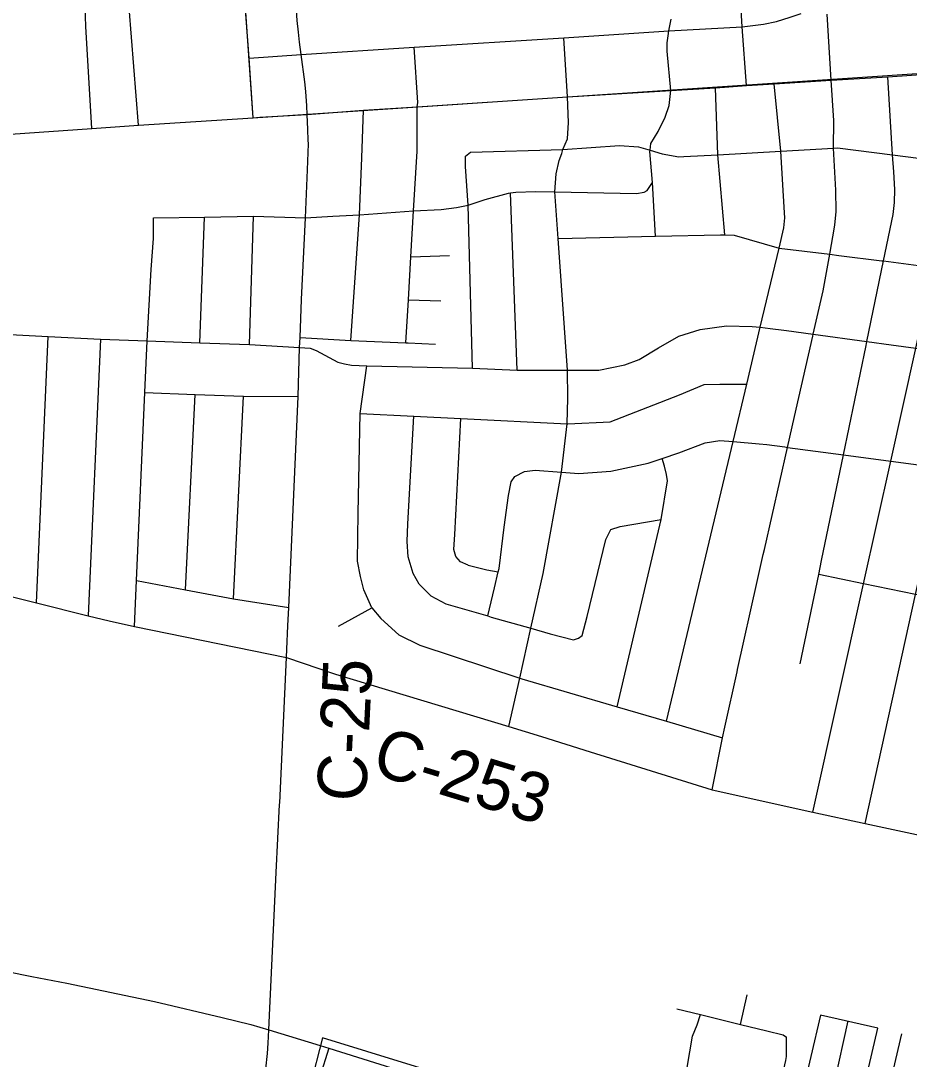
# Model space of a CAD drawing. Extents: x 114604 to 551442, y 316898 to 567001.
# Drawn here: x 179238 to 184654, y 374135 to 380464 of the extents above; entities that cross this region are included whole.
import ezdxf

# ---------------------------------------------------------------- set-up
doc = ezdxf.new("R2010")
doc.units = 0
for name, color, linetype in [('GE_P_Alignment_1000_Bearings', 7, 'Continuous'), ('GE_P_Alignment_1000_Cardinal_Points', 7, 'Continuous'), ('GE_P_Alignment_100_Cardinal_Points', 7, 'Continuous'), ('GE_P_Alignment_100_Stations', 7, 'Continuous'), ('GE_P_Alignment_500_Bearings', 7, 'Continuous'), ('PM_P_CL_Double_Solid', 7, 'Continuous')]:
    doc.layers.add(name, color=color, linetype=linetype)

msp = doc.modelspace()

# ---------------------------------------------------------------- linework, layer by layer
at = {"layer": 'GE_P_Alignment_1000_Bearings'}
msp.add_lwpolyline([(180378.1, 383822), (180652.5, 379872.3), (185830.5, 380217.5), (192483.8, 381831.8), (195789.4, 382643.8)], dxfattribs=at)
at = {"layer": 'GE_P_Alignment_1000_Cardinal_Points'}
for p, q in [((180242.2, 376996.6), (180301.3, 378187)), ((180534.3, 376941.6), (180595.8, 378175.4)), ((184046.5, 373297.2), (184282.2, 374369.4))]:
    msp.add_line(p, q, dxfattribs=at)
for points in [[(179930.4, 376772.8), (179943, 377053), (179994.6, 378199.2), (180009.2, 378512.3)], [(179994.6, 378199.2), (180301.3, 378187), (180595.8, 378175.4), (180928.6, 378174)], [(179943, 377053), (180242.2, 376996.6), (180534.3, 376941.6), (180871.4, 376888.8)], [(179777.4, 376805.9), (179930.4, 376772.8), (180857.5, 376583.8)], [(181115.8, 374201.6), (181061.3, 374027), (181007, 373892.1), (180965.1, 373818.1), (180956.9, 373777)]]:
    msp.add_lwpolyline(points, dxfattribs=at)
at = {"layer": 'GE_P_Alignment_100_Cardinal_Points'}
for p, q in [((184177.5, 380101.9), (184153.7, 380504.6)), ((182570.4, 380000.1), (182548.8, 380360.2)), ((181316.2, 379629.1), (181327, 379919)), ((182264.8, 378334.7), (182222.8, 379414.7)), ((180329.9, 378500.8), (180357.8, 379267.7)), ((180632, 378490.8), (180657, 379272.7)), ((181616.2, 379025.4), (181850.7, 379032.8)), ((181600.8, 378763.7), (181798.5, 378758)), ((179333.5, 376915.9), (179404.4, 378539.7)), ((179723.7, 378522.6), (179649, 376837.7)), ((181175.8, 376774.3), (181377.3, 376886.7)), ((183624.3, 374347.1), (183666.5, 374526.7))]:
    msp.add_line(p, q, dxfattribs=at)
for points in [[(180654.5, 379873.4), (180629.4, 380235.2), (180575.6, 380963.4), (180568.2, 381231.3), (180516.2, 381894.2), (180505.6, 382061.7), (180446, 382995.3), (180418, 383602.1), (180405.8, 383786.8)], [(183662, 380068.7), (183636.1, 380427.5), (183599.3, 381040.8), (183546, 381930.4)], [(179956, 379827.5), (179870.3, 380903.5), (179851.1, 381185.6), (179803.3, 381885.5)], [(180629.4, 380235.2), (180946.9, 380257.8), (181635.9, 380304.1), (182548.8, 380360.2), (183189.1, 380403), (183636.1, 380427.5), (183764.4, 380443.6), (183845.2, 380460.4), (183928.6, 380487), (183994.8, 380508.6)], [(183106.3, 379150.8), (183088.7, 379477.5), (183073.1, 379667.9), (183073.7, 379674.7), (183077.7, 379716.3), (183123.2, 379788.7), (183166, 379876.7), (183191.4, 379946.7), (183199.6, 380038.4), (183177.7, 380279.8), (183179.2, 380329.1), (183184.1, 380371.7), (183189.1, 380403), (183202.1, 380473.4)], [(180695.7, 379875.9), (180983.9, 379893.8), (181327, 379919), (181654.1, 379939.6), (182570.4, 380000.1), (183199.6, 380038.4), (183472, 380056), (183662, 380068.7), (183831.3, 380079.5), (184177.5, 380101.9), (184522.6, 380123.3), (184869.8, 380146.3), (185213.5, 380166.9), (185252.7, 380169.5), (185597, 380191.3), (185743.5, 380202), (185829.7, 380209.9), (185924.8, 380228.7), (185970, 380239.9), (186241.5, 380305.7), (186523.9, 380376), (186874.2, 380460.2), (186904.6, 380468)], [(181654.1, 379939.6), (181659.2, 379966.5), (181635.9, 380304.1)], [(184385.1, 375571.7), (184692.3, 376967), (184862, 377737.9), (185008.9, 378404.6), (185012.7, 378422.1), (185122, 378918.6), (185216.4, 379347.3), (185238.5, 379465.3), (185234.5, 379558.6), (185229.9, 379668.1), (185213.5, 380166.9)], [(183989.1, 376545.4), (184101.7, 377089.4), (184119.3, 377174.6), (184252.6, 377818.8), (184390.5, 378485.5), (184395.5, 378509.6), (184497, 378999.9), (184555.5, 379282.4), (184564.8, 379356.5), (184566.1, 379434.8), (184560, 379543.2), (184552.5, 379646.6), (184522.6, 380123.3)], [(184066.1, 375640.6), (184375, 377032.7), (184540.9, 377780.5), (184691.3, 378458.4), (184693.4, 378468.1), (184802.6, 378960.2), (184859.1, 379215), (184885, 379316.9), (184889.6, 379469.3), (184884.6, 379603.7), (184869.8, 380146.3)], [(184188.1, 379147.7), (184200.9, 379218.9), (184209.2, 379301.1), (184205.8, 379431.5), (184191.2, 379688.3), (184193.4, 379855.5), (184177.5, 380101.9)], [(183173.4, 376194.8), (183579.5, 377899.2), (183662.8, 378248.6), (183745.5, 378595.9), (183860.7, 379079), (183889.9, 379201.9), (183896.2, 379262.4), (183894.2, 379293.7), (183870.2, 379669.8), (183831.3, 380079.5)], [(183530.6, 379159), (183487, 379647.8), (183472, 380056)], [(182213.5, 376163.1), (182279.5, 376457.8), (182347.5, 376761.4), (182422.3, 377095), (182535, 377711.9), (182568.2, 378007.7), (182573, 378163.2), (182569.7, 378334.8), (182514.2, 379137.2), (182494.4, 379421.9), (182500.7, 379531.1), (182519, 379613.2), (182535.2, 379655.3), (182542.2, 379680.3), (182569.8, 379744.9), (182577.5, 379843.2), (182570.4, 380000.1)], [(181585.3, 378501.1), (181600.8, 378763.7), (181616.2, 379025.4), (181632.8, 379305.6), (181654.2, 379668.8), (181654.1, 379939.6)], [(177463.1, 379662.9), (178314.3, 379717.6), (178765.5, 379744.3), (179670.5, 379808.1), (179956, 379827.5), (180654.5, 379873.4), (180695.7, 379875.9)], [(181948.2, 379639), (181980.3, 379664), (182542.2, 379680.3), (182887.3, 379704.6), (183004, 379696), (183073.7, 379674.7), (183147.8, 379652.1), (183248.7, 379634.9), (183279.8, 379636.6), (183487, 379647.8), (183870.2, 379669.8), (184191.2, 379688.3), (184217, 379689.8), (184552.5, 379646.6), (184884.6, 379603.7)], [(181249.5, 378514.7), (181303.3, 379281.2), (181316.2, 379629.1)], [(181991.8, 378346.9), (181965.5, 379341), (181948.6, 379576.4), (181948.2, 379639)], [(180046.7, 379262.5), (180357.8, 379267.7), (180657, 379272.7), (180972.7, 379262.2), (181140, 379272.5), (181303.3, 379281.2), (181632.8, 379305.6), (181800.7, 379314.4), (181893.5, 379325.3), (181965.5, 379341), (182069.6, 379374.9), (182211, 379413.2), (182222.8, 379414.7), (182255.1, 379418.6), (182375.4, 379424.1), (182494.4, 379421.9), (182992.2, 379412.3), (183038.2, 379419.7), (183055.9, 379430.3), (183088.7, 379477.5)], [(180009.2, 378512.3), (180033.8, 378948.6), (180046.4, 379137.9), (180046.7, 379262.5)], [(182514.2, 379137.2), (183106.3, 379150.8), (183503.3, 379159.9), (183530.6, 379159), (183585.6, 379157.2), (183860.7, 379079), (184169, 379040.7), (184223.6, 379034)], [(184080.9, 378607.6), (184129.1, 378818.2), (184169, 379040.7), (184171.5, 379054.5), (184188.1, 379147.7)], [(184223.6, 379034), (184485.9, 379001.4), (184497, 378999.9), (184802.6, 378960.2), (185122, 378918.6), (185409.7, 378881.1)], [(177154, 378619.6), (177384.1, 378582.5), (177450.1, 378580.2), (177634.4, 378597.5), (177828.6, 378618.7), (177883.3, 378612.4), (178593.6, 378581.5), (179018, 378559.6), (179404.4, 378539.7), (179723.7, 378522.6), (180009.2, 378512.3), (180329.9, 378500.8), (180632, 378490.8), (180937.4, 378473.5)], [(180937.4, 378473.5), (181003.1, 378467.9), (181038.7, 378455.2), (181170.7, 378383.8), (181211.9, 378373.3), (181254.7, 378365), (181347.2, 378361.3), (181991.8, 378346.9), (182264.8, 378334.7), (182569.7, 378334.8), (182761.9, 378334.9), (182920.1, 378366.3), (183008.4, 378400), (183124.8, 378471.6), (183249.2, 378541.3), (183379.5, 378582.8), (183539.7, 378604.2), (183695.8, 378601.5), (183745.5, 378595.9), (183805.9, 378589), (183889.7, 378577.7), (183905.9, 378575.5)], [(183771.1, 377241.8), (183911.2, 377864.1), (183953.8, 378053), (184065.6, 378540.9), (184068.5, 378553.6), (184080.9, 378607.6)], [(183905.9, 378575.5), (184068.5, 378553.6), (184395.5, 378509.6), (184544.1, 378489.5), (184693.4, 378468.1), (185012.7, 378422.1), (185302, 378380.5)], [(180941.3, 378534.2), (181249.5, 378514.7), (181585.3, 378501.1)], [(181585.3, 378501.1), (181599.6, 378500.5), (181766, 378493.8)], [(181377.3, 376886.7), (181330, 376995.9), (181309.5, 377077.6), (181290.7, 377169.5), (181294.2, 377463), (181307.1, 378070.4), (181347.2, 378361.3)], [(181307.1, 378070.4), (181634.7, 378054.1), (181920.2, 378039.9), (182568.2, 378007.7), (182573.5, 378007.4), (182830.1, 378019.1), (183253, 378184.3), (183403.8, 378247.1), (183500.1, 378250), (183662.8, 378248.6)], [(181666.3, 377030), (181630.3, 377095.2), (181599.2, 377196.8), (181594.4, 377291.1), (181597.3, 377397.7), (181634.7, 378054.1)], [(181966.2, 377145.4), (181919.4, 377166.1), (181890.3, 377199.4), (181877, 377241.2), (181884.3, 377333.8), (181920.2, 378039.9)], [(182249.5, 377686.3), (182308.9, 377716.2), (182372.9, 377724.1), (182535, 377711.9), (182640.6, 377703.9), (182834.9, 377719.8), (183062.4, 377766.7), (183147.9, 377795.9), (183249.4, 377830.6), (183410.2, 377891.6), (183500.1, 377906.4), (183579.5, 377899.2), (183739.2, 377884.9), (183786, 377880.7), (183895.6, 377866.2), (183911.2, 377864.1), (184252.6, 377818.8), (184540.9, 377780.5), (184862, 377737.9)], [(182874.4, 376282.6), (183140.8, 377423.5), (183180.2, 377660.9), (183174.9, 377697.8), (183161.4, 377749.6), (183147.9, 377795.9)], [(176287.3, 377710.4), (176436.4, 377681.4), (176954.2, 377580.5), (176961, 377579.2), (177274.6, 377527.3), (177401.3, 377506.9), (177473.6, 377488.5), (177707.2, 377428.8), (177781.7, 377405.8), (177808, 377381.2), (177830.5, 377360.2), (177889.5, 377300.7), (177916, 377267), (177966.5, 377245.6), (178312.6, 377164), (178583.6, 377099.2), (178892.1, 377025.4), (179333.5, 376915.9), (179649, 376837.7), (179777.4, 376805.9)], [(182084.4, 376836.3), (182124.8, 377007.5), (182148.5, 377104.5), (182153.5, 377124.8), (182184.3, 377376.9), (182210.7, 377570.6), (182226.4, 377653.5), (182249.5, 377686.3)], [(182804.9, 377303), (182835.3, 377364.1), (182891, 377381.9), (183140.8, 377423.5)], [(182637.8, 376701.2), (182659.4, 376717.9), (182690.2, 376833.4), (182804.9, 377303)], [(183607.9, 376510.9), (183727.3, 377047.4), (183764.1, 377210.7), (183771.1, 377241.8)], [(181966.2, 377145.4), (182079.4, 377116.6), (182148.5, 377104.5)], [(187364, 376180.1), (187338.5, 376214.7), (187306.8, 376237.3), (187267.2, 376266), (187244, 376276.5), (187211.5, 376291.1), (187163.6, 376303), (186891.2, 376368.6), (186629.3, 376430.7), (186376.1, 376490.8), (186102.7, 376555.6), (185828.1, 376620.8), (185725.5, 376647.8), (185675.9, 376678.8), (185624.6, 376725.8), (185599.7, 376760.9), (185577.4, 376780.8), (185341.3, 376831.7), (185243.7, 376852.8), (184995.2, 376904.2), (184692.3, 376967), (184375, 377032.7), (184101.7, 377089.4)], [(181666.3, 377030), (181738.6, 376959.8), (181828.4, 376910.2), (182084.4, 376836.3), (182105.9, 376830), (182347.5, 376761.4), (182464.3, 376728.2), (182608, 376690.3), (182637.8, 376701.2)], [(181377.3, 376886.7), (181433.5, 376820.1), (181542.8, 376720.9), (181671.2, 376658.4), (182279.5, 376457.8), (182291.6, 376453.8), (182874.4, 376282.6), (183173.4, 376194.8), (183516.3, 376094)], [(183451.5, 375776.6), (183516.3, 376094), (183529.4, 376157.9), (183604.4, 376495.3), (183607.9, 376510.9)], [(183236.5, 374442.4), (183380.6, 374407), (183624.3, 374347.1), (183785.9, 374307.4), (183884.5, 374282.7), (183904.8, 374268.9)], [(183286.5, 373886.8), (183274, 373918.7), (183281.2, 373977.1), (183333.2, 374275), (183360.3, 374343.7), (183380.6, 374407)], [(183734, 373403.1), (183900.8, 374126.2), (183906.5, 374150.4), (183905.8, 374196.6), (183904.8, 374268.9)], [(184449.7, 373605.7), (184572.2, 374133.1), (184608.4, 374288.7)]]:
    msp.add_lwpolyline(points, dxfattribs=at)
at = {"layer": 'GE_P_Alignment_100_Stations'}
for points in [[(184309.4, 373670.1), (184461.6, 374323.3), (184112.8, 374402.9), (183877, 373395.6)], [(181915.2, 374006.9), (181077.5, 374264.2), (181002.9, 373972.1)]]:
    msp.add_lwpolyline(points, dxfattribs=at)
at = {"layer": 'GE_P_Alignment_500_Bearings'}
for points in [[(180980.8, 379945.5), (180975.3, 380033.4), (180970, 380091.6), (180946.9, 380257.8), (180936.2, 380334.2), (180930.4, 380395.5), (180922.5, 380466.7), (180876.5, 381175.9), (180821.6, 382102.7), (180771.7, 382923.8), (180763.4, 383055.1), (180727.8, 383596.2), (180730.1, 383657.4), (180737.9, 383698.2), (180752.5, 383748.5), (180775.2, 383797.6), (180826.7, 383814.3), (180868.8, 383822.7), (180917.7, 383824.4), (180926.8, 383873.4), (180921.2, 383990.9)], [(179670.5, 379808.1), (179634.8, 380429.3), (179629, 380613.5), (179628, 380747.8)], [(180990.9, 379736), (180988.2, 379800.9), (180983.9, 379893.8), (180980.8, 379945.5)], [(180859.6, 376634.2), (180865.6, 376775.6), (180871.4, 376888.8), (180928.6, 378174), (180937.4, 378473.5), (180941.3, 378534.2), (180949.2, 378764.6), (180972.7, 379262.2), (180986.2, 379555.5), (180991.9, 379714.3), (180990.9, 379736)], [(180815.8, 375687.6), (180816.3, 375698.2), (180857.5, 376583.8), (180859.6, 376634.2)], [(180857.5, 376583.8), (181151.1, 376482.9), (181156.2, 376481.4)], [(181156.2, 376481.4), (182213.5, 376163.1), (182411.5, 376101.3)], [(182411.5, 376101.3), (182708.6, 376008.6), (183451.5, 375776.6), (184066.1, 375640.6), (184385.1, 375571.7), (184699, 375503.9), (185033, 375430.7), (185275.8, 375377.6), (185530.8, 375321.8), (185805.2, 375261.7), (186339.9, 375145), (187134.1, 374971.6), (187829.6, 374820.2), (188102.8, 374756.6), (188424.5, 374681.8), (189187.4, 374504.2), (189409.5, 374452.5), (190359.6, 374251.5)], [(180750.5, 374313.6), (180755.4, 374445.4), (180760, 374532), (180795.3, 375271.9), (180815.8, 375687.6)], [(178215.4, 374974.9), (178315.3, 374917.4), (178412.5, 374867.4), (178508.6, 374829.4), (178609.3, 374798.8), (178708.2, 374773.6), (178855.1, 374733.2), (179002.4, 374699), (179305.7, 374638.7), (179519, 374597.8), (180053.9, 374487), (180465.2, 374389), (180639.5, 374345.4), (180750.5, 374313.6), (181063.6, 374217.6)], [(180697.7, 373895), (180712.1, 373950.8), (180725.7, 374017.2), (180732.4, 374075.6), (180741.9, 374168.7), (180746.9, 374232.1), (180750.5, 374313.6)], [(181063.6, 374217.6), (181115.8, 374201.6), (181602.2, 374050.4), (181935.4, 373946), (182400.7, 373805.4), (182980.1, 373632.9), (183287.5, 373547.2), (183420, 373507.6), (183734, 373403.1), (183847.8, 373363), (184046.5, 373297.2), (184369.1, 373184.2), (184415.1, 373168.8)]]:
    msp.add_lwpolyline(points, dxfattribs=at)

# ---------------------------------------------------------------- texts
at = {"layer": 'PM_P_CL_Double_Solid'}
for s, rotation, p in [('C-25', 87.32845, (181341.7, 375700.6)), ('C-253', 343.11424, (181366.2, 375878.8))]:
    msp.add_text(s, height=300.02, rotation=rotation, dxfattribs=at).set_placement(p)

doc.saveas('drawing.dxf')
